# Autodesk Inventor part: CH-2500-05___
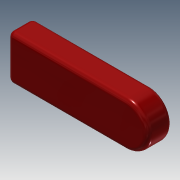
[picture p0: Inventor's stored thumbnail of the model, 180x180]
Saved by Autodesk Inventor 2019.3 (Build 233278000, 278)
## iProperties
Created: 2012-09
Part Number: CH-2500-05___
Material: Ogólny
Document SubType Name: Modeling
Designer: CADENGINEERING4
Density: 1 g/cm^3
Appearance: Czerwona
Author: CADENGINEERING4
Revision Number: ÈÎºÎ
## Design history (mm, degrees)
feature "NONE"
node "Bryła1"
